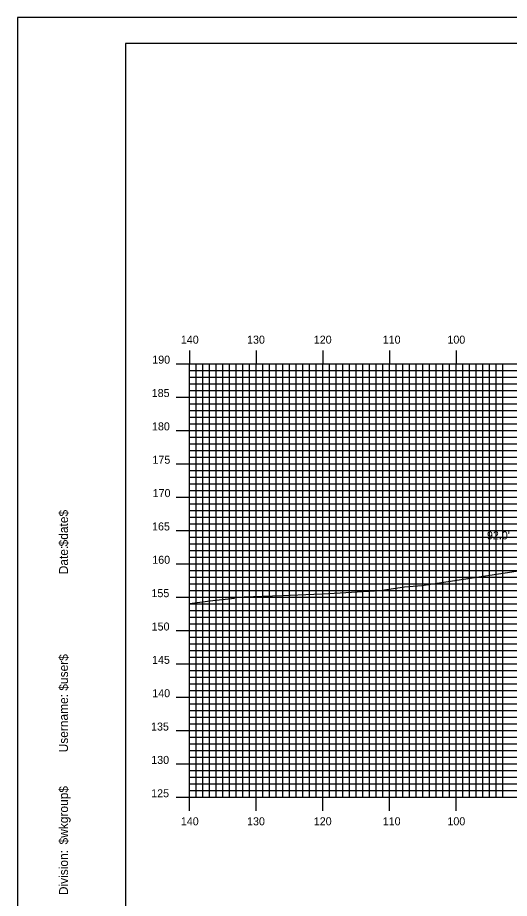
# Model space of a CAD drawing. Extents: x 1784221 to 1784564, y 442591 to 442811.
# Drawn here: x 1784221.2 to 1784295, y 442678.5 to 442810.5 of the extents above; entities that cross this region are included whole.
import ezdxf

# ---------------------------------------------------------------- set-up
doc = ezdxf.new("R2010")
doc.units = 0
for name, color, linetype in [('BORDER', 7, 'Continuous'), ('D_Text_Standard', 7, 'Continuous'), ('H_V ANNOTATION', 7, 'Continuous'), ('MAJOR', 7, 'Continuous'), ('MINOR', 7, 'Continuous'), ('PLOT BOUNDARY', 7, 'Continuous'), ('S_Roadway_Centerline', 7, 'Continuous')]:
    doc.layers.add(name, color=color, linetype=linetype)

msp = doc.modelspace()

# ---------------------------------------------------------------- linework, layer by layer
at = {"layer": 'BORDER'}
msp.add_lwpolyline([(1784237.4, 442596.67), (1784557.4, 442596.67), (1784557.4, 442806.67), (1784237.4, 442806.67)], close=True, dxfattribs=at)
at = {"layer": 'MAJOR'}
for p, q in [((1784247, 442760.67), (1784247, 442758.67)), ((1784257, 442760.67), (1784257, 442758.67)), ((1784267, 442760.67), (1784267, 442758.67)), ((1784277, 442760.67), (1784277, 442758.67)), ((1784287, 442760.67), (1784287, 442758.67)), ((1784245, 442758.67), (1784247, 442758.67)), ((1784247, 442758.67), (1784527, 442758.67)), ((1784247, 442693.67), (1784247, 442758.67)), ((1784247, 442693.67), (1784247, 442758.67)), ((1784247, 442758.67), (1784527, 442758.67)), ((1784257, 442693.67), (1784257, 442758.67)), ((1784267, 442693.67), (1784267, 442758.67)), ((1784277, 442693.67), (1784277, 442758.67)), ((1784287, 442693.67), (1784287, 442758.67)), ((1784245, 442753.67), (1784247, 442753.67)), ((1784247, 442753.67), (1784527, 442753.67)), ((1784245, 442748.67), (1784247, 442748.67)), ((1784247, 442748.67), (1784527, 442748.67)), ((1784245, 442743.67), (1784247, 442743.67)), ((1784247, 442743.67), (1784527, 442743.67)), ((1784245, 442738.67), (1784247, 442738.67)), ((1784247, 442738.67), (1784527, 442738.67)), ((1784245, 442733.67), (1784247, 442733.67)), ((1784247, 442733.67), (1784527, 442733.67)), ((1784245, 442728.67), (1784247, 442728.67)), ((1784247, 442728.67), (1784527, 442728.67)), ((1784245, 442723.67), (1784247, 442723.67)), ((1784247, 442723.67), (1784527, 442723.67)), ((1784245, 442718.67), (1784247, 442718.67)), ((1784247, 442718.67), (1784527, 442718.67)), ((1784245, 442713.67), (1784247, 442713.67)), ((1784247, 442713.67), (1784527, 442713.67)), ((1784245, 442708.67), (1784247, 442708.67)), ((1784247, 442708.67), (1784527, 442708.67)), ((1784245, 442703.67), (1784247, 442703.67)), ((1784247, 442703.67), (1784527, 442703.67)), ((1784245, 442698.67), (1784247, 442698.67)), ((1784247, 442698.67), (1784527, 442698.67)), ((1784245, 442693.67), (1784247, 442693.67)), ((1784247, 442693.67), (1784527, 442693.67)), ((1784247, 442693.67), (1784527, 442693.67)), ((1784247, 442691.66), (1784247, 442693.67)), ((1784257, 442691.66), (1784257, 442693.67)), ((1784267, 442691.66), (1784267, 442693.67)), ((1784277, 442691.66), (1784277, 442693.67)), ((1784287, 442691.66), (1784287, 442693.67))]:
    msp.add_line(p, q, dxfattribs=at)
at = {"layer": 'MINOR'}
for p, q in [((1784247, 442757.67), (1784527, 442757.67)), ((1784247, 442757.67), (1784249, 442757.67)), ((1784248, 442693.67), (1784248, 442758.67)), ((1784249, 442693.67), (1784249, 442758.67)), ((1784250, 442693.67), (1784250, 442758.67)), ((1784251, 442693.67), (1784251, 442758.67)), ((1784252, 442693.67), (1784252, 442758.67)), ((1784253, 442693.67), (1784253, 442758.67)), ((1784254, 442693.67), (1784254, 442758.67)), ((1784255, 442693.67), (1784255, 442758.67)), ((1784256, 442693.67), (1784256, 442758.67)), ((1784258, 442693.67), (1784258, 442758.67)), ((1784259, 442693.67), (1784259, 442758.67)), ((1784260, 442693.67), (1784260, 442758.67)), ((1784261, 442693.67), (1784261, 442758.67)), ((1784262, 442693.67), (1784262, 442758.67)), ((1784263, 442693.67), (1784263, 442758.67)), ((1784264, 442693.67), (1784264, 442758.67)), ((1784265, 442693.67), (1784265, 442758.67)), ((1784266, 442693.67), (1784266, 442758.67)), ((1784268, 442693.67), (1784268, 442758.67)), ((1784269, 442693.67), (1784269, 442758.67)), ((1784270, 442693.67), (1784270, 442758.67)), ((1784271, 442693.67), (1784271, 442758.67)), ((1784272, 442693.67), (1784272, 442758.67)), ((1784273, 442693.67), (1784273, 442758.67)), ((1784274, 442693.67), (1784274, 442758.67)), ((1784275, 442693.67), (1784275, 442758.67)), ((1784276, 442693.67), (1784276, 442758.67)), ((1784278, 442693.67), (1784278, 442758.67)), ((1784279, 442693.67), (1784279, 442758.67)), ((1784280, 442693.67), (1784280, 442758.67)), ((1784281, 442693.67), (1784281, 442758.67)), ((1784282, 442693.67), (1784282, 442758.67)), ((1784283, 442693.67), (1784283, 442758.67)), ((1784284, 442693.67), (1784284, 442758.67)), ((1784285, 442693.67), (1784285, 442758.67)), ((1784286, 442693.67), (1784286, 442758.67)), ((1784288, 442693.67), (1784288, 442758.67)), ((1784289, 442693.67), (1784289, 442758.67)), ((1784290, 442693.67), (1784290, 442758.67)), ((1784291, 442693.67), (1784291, 442758.67)), ((1784292, 442693.67), (1784292, 442758.67)), ((1784293, 442693.67), (1784293, 442758.67)), ((1784294, 442693.67), (1784294, 442758.67)), ((1784247, 442756.67), (1784527, 442756.67)), ((1784247, 442756.67), (1784249, 442756.67)), ((1784247, 442755.67), (1784527, 442755.67)), ((1784247, 442755.67), (1784249, 442755.67)), ((1784247, 442754.67), (1784527, 442754.67)), ((1784247, 442754.67), (1784249, 442754.67)), ((1784247, 442752.67), (1784527, 442752.67)), ((1784247, 442752.67), (1784249, 442752.67)), ((1784247, 442751.67), (1784527, 442751.67)), ((1784247, 442751.67), (1784249, 442751.67)), ((1784247, 442750.67), (1784527, 442750.67)), ((1784247, 442750.67), (1784249, 442750.67)), ((1784247, 442749.67), (1784527, 442749.67)), ((1784247, 442749.67), (1784249, 442749.67)), ((1784247, 442747.67), (1784527, 442747.67)), ((1784247, 442747.67), (1784249, 442747.67)), ((1784247, 442746.67), (1784527, 442746.67)), ((1784247, 442746.67), (1784249, 442746.67)), ((1784247, 442745.67), (1784527, 442745.67)), ((1784247, 442745.67), (1784249, 442745.67)), ((1784247, 442744.67), (1784527, 442744.67)), ((1784247, 442744.67), (1784249, 442744.67)), ((1784247, 442742.67), (1784527, 442742.67)), ((1784247, 442742.67), (1784249, 442742.67)), ((1784247, 442741.67), (1784527, 442741.67)), ((1784247, 442741.67), (1784249, 442741.67)), ((1784247, 442740.67), (1784527, 442740.67)), ((1784247, 442740.67), (1784249, 442740.67)), ((1784247, 442739.67), (1784527, 442739.67)), ((1784247, 442739.67), (1784249, 442739.67)), ((1784247, 442737.67), (1784527, 442737.67)), ((1784247, 442737.67), (1784249, 442737.67)), ((1784247, 442736.67), (1784527, 442736.67)), ((1784247, 442736.67), (1784249, 442736.67)), ((1784247, 442735.67), (1784527, 442735.67)), ((1784247, 442735.67), (1784249, 442735.67)), ((1784247, 442734.67), (1784527, 442734.67)), ((1784247, 442734.67), (1784249, 442734.67)), ((1784247, 442732.67), (1784527, 442732.67)), ((1784247, 442732.67), (1784249, 442732.67)), ((1784247, 442731.67), (1784527, 442731.67)), ((1784247, 442731.67), (1784249, 442731.67)), ((1784247, 442730.67), (1784527, 442730.67)), ((1784247, 442730.67), (1784249, 442730.67)), ((1784247, 442729.67), (1784527, 442729.67)), ((1784247, 442729.67), (1784249, 442729.67)), ((1784247, 442727.67), (1784527, 442727.67)), ((1784247, 442727.67), (1784249, 442727.67)), ((1784247, 442726.67), (1784527, 442726.67)), ((1784247, 442726.67), (1784249, 442726.67)), ((1784247, 442725.67), (1784527, 442725.67)), ((1784247, 442725.67), (1784249, 442725.67)), ((1784247, 442724.67), (1784527, 442724.67)), ((1784247, 442724.67), (1784249, 442724.67)), ((1784247, 442722.67), (1784527, 442722.67)), ((1784247, 442722.67), (1784249, 442722.67)), ((1784247, 442721.67), (1784527, 442721.67)), ((1784247, 442721.67), (1784249, 442721.67)), ((1784247, 442720.67), (1784527, 442720.67)), ((1784247, 442720.67), (1784249, 442720.67)), ((1784247, 442719.67), (1784527, 442719.67)), ((1784247, 442719.67), (1784249, 442719.67)), ((1784247, 442717.67), (1784527, 442717.67)), ((1784247, 442717.67), (1784249, 442717.67)), ((1784247, 442716.67), (1784527, 442716.67)), ((1784247, 442716.67), (1784249, 442716.67)), ((1784247, 442715.67), (1784527, 442715.67)), ((1784247, 442715.67), (1784249, 442715.67)), ((1784247, 442714.67), (1784527, 442714.67)), ((1784247, 442714.67), (1784249, 442714.67)), ((1784247, 442712.67), (1784527, 442712.67)), ((1784247, 442712.67), (1784249, 442712.67)), ((1784247, 442711.67), (1784527, 442711.67)), ((1784247, 442711.67), (1784249, 442711.67)), ((1784247, 442710.67), (1784527, 442710.67)), ((1784247, 442710.67), (1784249, 442710.67)), ((1784247, 442709.67), (1784527, 442709.67)), ((1784247, 442709.67), (1784249, 442709.67)), ((1784247, 442707.67), (1784527, 442707.67)), ((1784247, 442707.67), (1784249, 442707.67)), ((1784247, 442706.67), (1784527, 442706.67)), ((1784247, 442706.67), (1784249, 442706.67)), ((1784247, 442705.67), (1784527, 442705.67)), ((1784247, 442705.67), (1784249, 442705.67)), ((1784247, 442704.67), (1784527, 442704.67)), ((1784247, 442704.67), (1784249, 442704.67)), ((1784247, 442702.67), (1784527, 442702.67)), ((1784247, 442702.67), (1784249, 442702.67)), ((1784247, 442701.67), (1784527, 442701.67)), ((1784247, 442701.67), (1784249, 442701.67)), ((1784247, 442700.67), (1784527, 442700.67)), ((1784247, 442700.67), (1784249, 442700.67)), ((1784247, 442699.67), (1784527, 442699.67)), ((1784247, 442699.67), (1784249, 442699.67)), ((1784247, 442697.67), (1784527, 442697.67)), ((1784247, 442697.67), (1784249, 442697.67)), ((1784247, 442696.67), (1784527, 442696.67)), ((1784247, 442696.67), (1784249, 442696.67)), ((1784247, 442695.67), (1784527, 442695.67)), ((1784247, 442695.67), (1784249, 442695.67)), ((1784247, 442694.67), (1784527, 442694.67)), ((1784247, 442694.67), (1784249, 442694.67))]:
    msp.add_line(p, q, dxfattribs=at)
at = {"layer": 'PLOT BOUNDARY'}
msp.add_lwpolyline([(1784221.21, 442590.55), (1784561.21, 442590.55), (1784561.21, 442810.55), (1784221.21, 442810.55)], close=True, dxfattribs=at)
at = {"layer": 'S_Roadway_Centerline'}
msp.add_lwpolyline([(1784247, 442722.73), (1784250.48, 442723.19), (1784253.75, 442723.51), (1784253.77, 442723.65), (1784260.87, 442723.92), (1784265.65, 442724.12), (1784267.01, 442724.15), (1784275.6, 442724.68), (1784279.22, 442725.2), (1784281.85, 442725.43), (1784301.59, 442728.41)], dxfattribs=at)

# ---------------------------------------------------------------- texts
at = {"layer": 'BORDER'}
for s, p in [('$date$', (1784228.77, 442731.28)), ('$date$', (1784228.77, 442731.28)), ('Date:', (1784228.77, 442727.1)), ('Date:', (1784228.77, 442727.1)), ('$user$', (1784228.77, 442709.65)), ('$user$', (1784228.77, 442709.65)), ('Username:', (1784228.77, 442700.4)), ('Username:', (1784228.77, 442700.4)), ('$wkgroup$', (1784228.77, 442686.6)), ('$wkgroup$', (1784228.77, 442686.6)), ('Division:', (1784228.77, 442679)), ('Division:', (1784228.77, 442679))]:
    msp.add_text(s, height=1.339, rotation=90, dxfattribs=at).set_placement(p)
at = {"layer": 'D_Text_Standard'}
msp.add_text("92.0'", height=1.2, dxfattribs=at).set_placement((1784291.61, 442732.33))
at = {"layer": 'H_V ANNOTATION'}
for s, p in [('140', (1784245.7, 442761.67)), ('130', (1784255.63, 442761.67)), ('120', (1784265.64, 442761.67)), ('110', (1784275.98, 442761.67)), ('100', (1784285.68, 442761.67)), ('190', (1784241.41, 442758.67)), ('185', (1784241.33, 442753.67)), ('180', (1784241.37, 442748.67)), ('175', (1784241.44, 442743.67)), ('170', (1784241.47, 442738.67)), ('165', (1784241.38, 442733.67)), ('160', (1784241.41, 442728.67)), ('155', (1784241.29, 442723.67)), ('150', (1784241.32, 442718.67)), ('145', (1784241.38, 442713.67)), ('140', (1784241.41, 442708.67)), ('135', (1784241.23, 442703.67)), ('130', (1784241.26, 442698.67)), ('125', (1784241.25, 442693.67)), ('140', (1784245.7, 442689.47)), ('130', (1784255.63, 442689.47)), ('120', (1784265.64, 442689.47)), ('110', (1784275.98, 442689.47)), ('100', (1784285.68, 442689.47))]:
    msp.add_text(s, height=1.2, dxfattribs=at).set_placement(p)
at = {"layer": 'MAJOR'}
msp.add_text('-', height=0.012, dxfattribs=at).set_placement((1784246.99, 442693.67))

doc.saveas('drawing.dxf')
